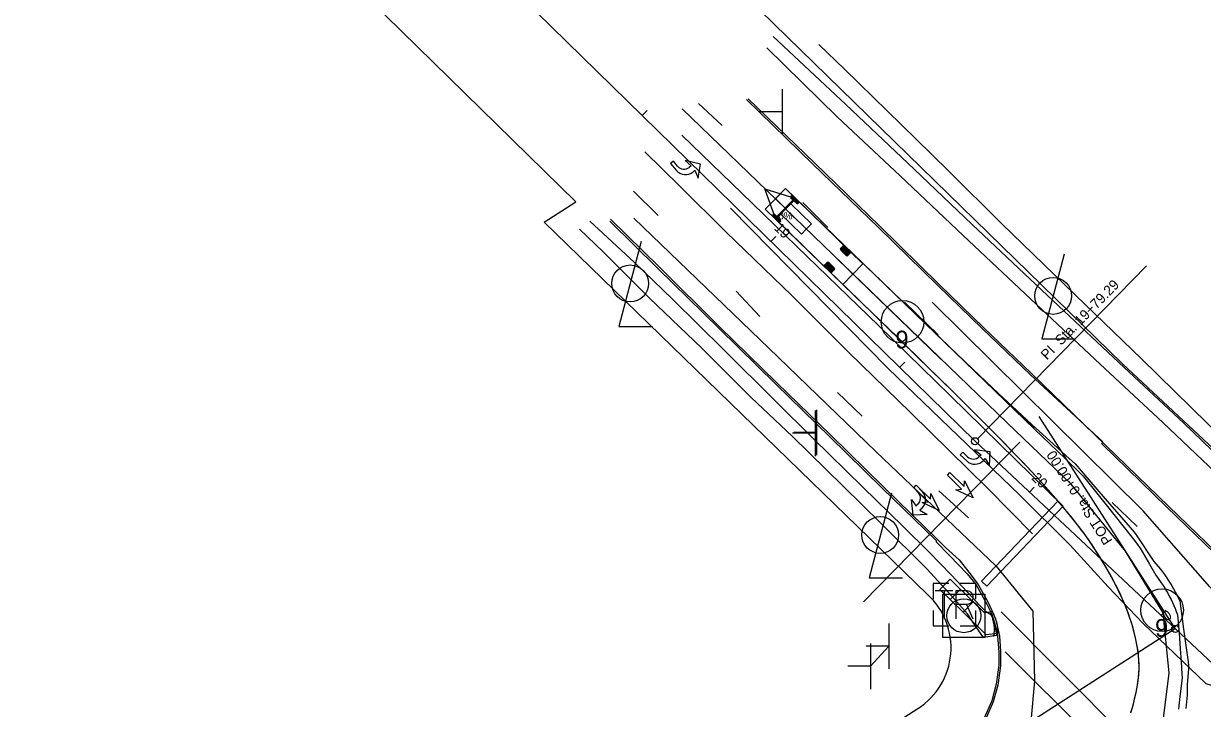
# Model space of a CAD drawing. Extents: x 1475900 to 1484331, y 375914 to 383395.
# Drawn here: x 1479302.4 to 1479629.9, y 379915.4 to 380105.5 of the extents above; entities that cross this region are included whole.
import ezdxf

# ---------------------------------------------------------------- set-up
doc = ezdxf.new("R2010")
doc.units = 0
for name, color, linetype in [('Default', 7, 'Continuous'), ('LT_X_Poles', 7, 'Continuous'), ('PM_X_Cells', 7, 'Continuous'), ('PM_X_Cells (Construction)', 7, 'Continuous'), ('PM_X_Channelizing_Line', 7, 'Continuous'), ('PM_X_CL_Double_Solid', 7, 'Continuous'), ('PM_X_Crosswalk', 7, 'Continuous'), ('PM_X_Lane_Line', 7, 'Continuous'), ('PM_X_Misc', 7, 'Continuous'), ('PM_X_Stop_Line', 7, 'Continuous'), ('PV_X_Curb', 7, 'Continuous'), ('PV_X_Walk', 7, 'Continuous'), ('RW_X_CL_20', 7, 'Continuous'), ('RW_X_Esmt_SH', 7, 'Continuous'), ('RW_X_Esmt_U', 7, 'Continuous'), ('RW_X_Text', 7, 'Continuous'), ('SG_X_Poles', 7, 'Continuous'), ('SG_X_PullBox', 7, 'Continuous'), ('SG_X_PullBox (Construction)', 7, 'Continuous'), ('SN_X_Public', 7, 'Continuous')]:
    doc.layers.add(name, color=color, linetype=linetype)

# ---------------------------------------------------------------- blocks, each defined once
blk = doc.blocks.new('SGN1P')
at = {"layer": 'SN_X_Public'}
for p, q in [((0, 0.02032), (0, -0.02032)), ((0, 0), (-0.02032, 0))]:
    blk.add_line(p, q, dxfattribs=at)
blk = doc.blocks.new('POINT_DISPLAY')
at = {"layer": 'Default'}
blk.add_line((0, 0), (0, 0), dxfattribs=at)
blk = doc.blocks.new('PMTHR')
at = {"layer": 'PM_X_Cells'}
blk.add_lwpolyline([(0, 0), (-1.27, -0.441), (-1.016, -0.127), (-2.413, -0.127), (-2.413, 0.127), (-1.016, 0.127), (-1.27, 0.441)], close=True, dxfattribs=at)
at = {"layer": 'PM_X_Cells (Construction)'}
for p in [(0, 0), (-2.413, 0)]:
    blk.add_blockref('POINT_DISPLAY', p, dxfattribs=at)
blk = doc.blocks.new('PMLFT')
at = {"layer": 'PM_X_Cells'}
for points in [[(-0.569, 0), (-0.569, 0), (-0.569, 0.169), (0, 0), (-0.65, 0.762), (-1.544, 0.085), (-0.975, 0.169), (-0.975, -0.009)], [(-1.559, -0.593), (-2.032, -0.593), (-2.032, -0.847), (-1.402, -0.847)]]:
    blk.add_lwpolyline(points, dxfattribs=at)
for centre, radius, end in [((-1.559, -0.009), 0.583, 0), ((-1.402, -0.013), 0.833, 0.90849)]:
    blk.add_arc(centre, radius, 270, end, dxfattribs=at)
at = {"layer": 'PM_X_Cells (Construction)'}
for p in [(-2.032, 0), (0, 0)]:
    blk.add_blockref('POINT_DISPLAY', p, dxfattribs=at)
blk = doc.blocks.new('LPOLE')
at = {"layer": 'LT_X_Poles'}
blk.add_lwpolyline([(0.01, 0.0375), (-0.01, -0.0385), (0.02, -0.0385)], dxfattribs=at)
blk.add_circle((0, 0), 0.0165, dxfattribs=at)
blk = doc.blocks.new('SPOLE')
at = {"layer": 'SG_X_Poles'}
blk.add_lwpolyline([(-0.0191, -0.0191), (0.019, -0.0191), (0.019, 0.019), (-0.0191, 0.019)], close=True, dxfattribs=at)
blk.add_circle((0, 0), 0.0152, dxfattribs=at)
blk = doc.blocks.new('SIGPB')
at = {"layer": 'SG_X_PullBox'}
for p, q in [((-0.0172, 0.0127), (-0.0014, 0.0127)), ((-0.0092, 0.0127), (-0.0092, -0.0127)), ((0.0108, 0.0003), (0.0164, -0.0127))]:
    blk.add_line(p, q, dxfattribs=at)
for points in [[(-0.0051, 0.019), (-0.019, 0.019), (-0.019, 0.0051)], [(0.0014, -0.0127), (0.0014, 0.0127), (0.011, 0.0127), (0.012, 0.0125), (0.0134, 0.0121), (0.014, 0.0117), (0.0146, 0.0113), (0.0154, 0.0103), (0.016, 0.0093), (0.0164, 0.0077), (0.0164, 0.0053), (0.0162, 0.0045), (0.0158, 0.0033), (0.015, 0.0019), (0.0142, 0.0013), (0.0136, 0.0009), (0.0132, 0.0007), (0.0126, 0.0005), (0.0108, 0.0003), (0.0014, 0.0003)], [(0.019, 0.0051), (0.019, 0.019), (0.0051, 0.019)], [(-0.019, -0.0051), (-0.019, -0.019), (-0.0051, -0.019)], [(0.0051, -0.019), (0.019, -0.019), (0.019, -0.0051)]]:
    blk.add_lwpolyline(points, dxfattribs=at)
at = {"layer": 'SG_X_PullBox (Construction)'}
blk.add_blockref('POINT_DISPLAY', (0, 0), dxfattribs=at)

msp = doc.modelspace()

# ---------------------------------------------------------------- linework, layer by layer
at = {"layer": 'Default'}
for p, q in [((1479535.72, 379945), (1479579.16, 379989.25)), ((1479542.75, 379932.65), (1479537.69, 379927.08))]:
    msp.add_line(p, q, dxfattribs=at)
at = {"layer": 'PM_X_Cells'}
for points in [[(1479564.64, 379985.22), (1479563.29, 379986.5), (1479562.6, 379985.78), (1479564.4, 379984.07)], [(1479569.08, 379984.23), (1479569.08, 379984.23), (1479569.53, 379984.72), (1479570.7, 379982.69), (1479570.91, 379986.63), (1479566.52, 379987.12), (1479568.37, 379985.82), (1479567.89, 379985.31)], [(1479550.93, 379975.28), (1479549.66, 379976.64), (1479550.39, 379977.33), (1479552.08, 379975.52)], [(1479551.89, 379970.85), (1479551.9, 379970.85), (1479551.41, 379970.39), (1479553.43, 379969.21), (1479549.49, 379969.03), (1479549.03, 379973.42), (1479550.31, 379971.56), (1479550.83, 379972.04)]]:
    msp.add_lwpolyline(points, dxfattribs=at)
for centre, radius, start, end in [((1479566.66, 379986.45), 3.28, 226.5201, 317.4286), ((1479566.22, 379986.89), 2.3, 226.5201, 316.5201), ((1479549.26, 379973.71), 2.3, 313.1325, 43.1325), ((1479549.69, 379973.28), 3.28, 312.224, 43.1325)]:
    msp.add_arc(centre, radius, start, end, dxfattribs=at)
at = {"layer": 'PM_X_Channelizing_Line'}
msp.add_lwpolyline([(1479582.67, 379963.81), (1479570.27, 379976.46), (1479548.91, 379997.46), (1479531.64, 380014.2), (1479515.85, 380030.02), (1479497.57, 380047.61), (1479484.7, 380060.36), (1479474.97, 380069.83)], dxfattribs=at)
at = {"layer": 'PM_X_CL_Double_Solid'}
msp.add_lwpolyline([(1479591.18, 379971.53), (1479573.51, 379988.81), (1479559.79, 380002.28), (1479539.85, 380021.68), (1479520.04, 380040.81), (1479501.88, 380058.4), (1479485.22, 380074.47)], dxfattribs=at)
at = {"layer": 'PM_X_Crosswalk'}
for p, q in [((1479636.37, 379879.55), (1479574.01, 379942.24)), ((1479627.79, 379878.68), (1479575.12, 379931.13))]:
    msp.add_line(p, q, dxfattribs=at)
at = {"layer": 'PM_X_Lane_Line'}
for p, q in [((1479489.87, 380083.25), (1479496.48, 380077.17)), ((1479471.84, 380058.98), (1479478.64, 380052.19)), ((1479518.91, 380055.83), (1479525.77, 380048.89)), ((1479500.33, 380031.19), (1479506.91, 380024.21)), ((1479547.14, 380028.17), (1479556.49, 380019.06)), ((1479528.47, 380003.04), (1479535.32, 379996.48)), ((1479576.69, 379999.46), (1479583.1, 379993.39)), ((1479556.63, 379975.74), (1479564.85, 379968.3)), ((1479604.82, 379972.58), (1479611.79, 379965.86))]:
    msp.add_line(p, q, dxfattribs=at)
at = {"layer": 'PM_X_Misc'}
for p, q in [((1479485.35, 380081.84), (1479514.11, 380054.03)), ((1479511.23, 380051.56), (1479516.56, 380056.9)), ((1479516.56, 380051.56), (1479511.23, 380056.9)), ((1479557.24, 380012.32), (1479528.48, 380040.12))]:
    msp.add_line(p, q, dxfattribs=at)
for points in [[(1479519.86, 380048.47), (1479518.47, 380047.03), (1479512.72, 380052.59), (1479511.33, 380051.15), (1479508.35, 380059.58), (1479516.88, 380056.91), (1479515.49, 380055.47), (1479521.25, 380049.91)], [(1479514.01, 380059.68), (1479535.58, 380038.83), (1479532.8, 380035.95), (1479530.01, 380033.08), (1479508.45, 380053.93), (1479511.23, 380056.81)]]:
    msp.add_lwpolyline(points, close=True, dxfattribs=at)
for points in [[(1479609.95, 379914.15), (1479610.41, 379915.64), (1479610.82, 379917.12), (1479611.17, 379918.62), (1479611.34, 379919.37), (1479611.64, 379920.87), (1479611.9, 379922.37), (1479612.01, 379923.12), (1479612.19, 379924.67), (1479612.28, 379926.19), (1479612.3, 379926.95), (1479612.25, 379928.49), (1479612.15, 379930), (1479611.95, 379931.53), (1479611.7, 379933.03), (1479611.4, 379934.52), (1479611.23, 379935.26), (1479610.66, 379937.51), (1479610.23, 379939), (1479609.75, 379940.47), (1479609.51, 379941.2), (1479608.97, 379942.63), (1479608.41, 379944.06), (1479607.81, 379945.46), (1479607.18, 379946.85), (1479606.52, 379948.22), (1479605.83, 379949.58), (1479605.13, 379950.93), (1479604.03, 379952.94), (1479602.88, 379954.93), (1479601.7, 379956.9), (1479600.48, 379958.86), (1479599.22, 379960.79), (1479597.91, 379962.69), (1479596.55, 379964.55), (1479595.16, 379966.39), (1479593.72, 379968.21), (1479591.76, 379970.61), (1479589.75, 379972.98), (1479588.25, 379974.7), (1479586.21, 379976.99), (1479583.63, 379979.81), (1479580.99, 379982.62), (1479578.35, 379985.4), (1479574.6, 379989.26), (1479570.82, 379993.11), (1479565.93, 379998), (1479560.47, 380003.42), (1479554.46, 380009.32), (1479546.21, 380017.37), (1479534.61, 380028.62), (1479514.41, 380048.17), (1479508.45, 380053.93), (1479514.01, 380059.68), (1479543.55, 380031.2), (1479557.19, 380018.1), (1479566.13, 380009.55), (1479573.34, 380002.71), (1479576.98, 379999.3), (1479582.51, 379994.18), (1479587.5, 379989.62), (1479591.94, 379985.61), (1479594.51, 379983.3), (1479595.09, 379982.67), (1479599.48, 379977.51), (1479603.41, 379972.95), (1479608, 379967.67), (1479610.94, 379964.31), (1479611.48, 379963.6), (1479616.41, 379956.2), (1479618.2, 379954.04), (1479618.77, 379953.29), (1479619.33, 379952.54), (1479619.87, 379951.77), (1479620.39, 379950.99), (1479620.9, 379950.2), (1479621.39, 379949.39), (1479621.86, 379948.58), (1479622.32, 379947.76), (1479622.75, 379946.93), (1479623.17, 379946.09), (1479623.57, 379945.24), (1479624.65, 379937.36), (1479625.89, 379928.29), (1479626, 379927.35), (1479626.02, 379926.44), (1479625.63, 379921.93), (1479625.64, 379920.99), (1479625.63, 379920.05), (1479625.6, 379919.11), (1479625.55, 379918.17), (1479625.48, 379917.24), (1479625.38, 379916.3), (1479625.27, 379915.37)], [(1479610.01, 379914.32), (1479610.42, 379915.64), (1479610.79, 379917.01), (1479611.13, 379918.4), (1479611.44, 379919.83), (1479611.71, 379921.28), (1479611.96, 379922.76), (1479612.12, 379923.97), (1479612.23, 379925.19), (1479612.29, 379926.41), (1479612.3, 379927.63), (1479612.25, 379928.85), (1479612.15, 379930.07), (1479611.99, 379931.29), (1479611.77, 379932.67), (1479611.5, 379934.07), (1479611.18, 379935.48), (1479610.82, 379936.9), (1479610.43, 379938.33), (1479610.02, 379939.7), (1479609.57, 379941.04), (1479609.07, 379942.4), (1479608.53, 379943.76), (1479607.95, 379945.13), (1479607.34, 379946.5), (1479606.69, 379947.87), (1479606.01, 379949.24), (1479605.3, 379950.61), (1479604.19, 379952.65), (1479603.02, 379954.69), (1479601.81, 379956.72), (1479600.56, 379958.74), (1479599.74, 379960.01), (1479598.89, 379961.29), (1479598.01, 379962.55), (1479596.64, 379964.44), (1479595.22, 379966.31), (1479593.75, 379968.17), (1479592.25, 379970.02), (1479590.72, 379971.85), (1479589.15, 379973.67), (1479587.02, 379976.08), (1479584.86, 379978.47), (1479582.66, 379980.85), (1479579.87, 379983.8), (1479577.06, 379986.74), (1479573.65, 379990.24), (1479569.63, 379994.3), (1479565.01, 379998.92), (1479559.77, 380004.1), (1479553.34, 380010.41), (1479545.13, 380018.42), (1479533.36, 380029.84), (1479511.33, 380051.15), (1479516.89, 380056.9), (1479583.23, 379992.88), (1479591.71, 379984.73), (1479595.98, 379980.59), (1479596.61, 379979.97), (1479597.17, 379979.32), (1479603.51, 379971.43), (1479607.77, 379966.08), (1479610.97, 379961.99), (1479612.05, 379960.59), (1479612.54, 379959.86), (1479615.18, 379955.4), (1479616.92, 379952.42), (1479618.46, 379950.24), (1479618.95, 379949.49), (1479619.43, 379948.73), (1479619.88, 379947.96), (1479620.33, 379947.18), (1479620.75, 379946.39), (1479621.16, 379945.6), (1479621.55, 379944.79), (1479621.92, 379943.97), (1479622.28, 379943.15), (1479622.62, 379942.32), (1479622.96, 379941.38), (1479623.4, 379936.24), (1479623.74, 379931.9), (1479623.99, 379928.4), (1479624.2, 379924.87), (1479624.25, 379923.94), (1479624.2, 379923.03), (1479623.56, 379918.74), (1479623.5, 379917.85), (1479623.42, 379916.96), (1479623.32, 379916.07), (1479623.2, 379915.18)], [(1479515.46, 380057.44), (1479517.48, 380055.5), (1479517.62, 380055.64), (1479515.6, 380057.59), (1479515.74, 380057.73), (1479517.75, 380055.79), (1479517.8, 380055.83), (1479517.64, 380056.17), (1479516.13, 380057.63), (1479515.79, 380057.78), (1479515.42, 380057.4), (1479515.58, 380057.06), (1479517.09, 380055.6), (1479517.43, 380055.45), (1479517.8, 380055.83)], [(1479510.46, 380052.27), (1479512.47, 380050.32), (1479512.61, 380050.47), (1479510.6, 380052.41), (1479510.73, 380052.56), (1479512.75, 380050.61), (1479512.8, 380050.66), (1479512.64, 380051), (1479511.13, 380052.46), (1479510.78, 380052.6), (1479510.41, 380052.22), (1479510.57, 380051.88), (1479512.08, 380050.42), (1479512.43, 380050.28), (1479512.8, 380050.66)], [(1479529.28, 380042.97), (1479531.3, 380041.02), (1479531.44, 380041.16), (1479529.42, 380043.11), (1479529.56, 380043.25), (1479531.57, 380041.31), (1479531.62, 380041.35), (1479531.46, 380041.69), (1479529.95, 380043.15), (1479529.61, 380043.3), (1479529.24, 380042.92), (1479529.4, 380042.58), (1479530.91, 380041.12), (1479531.25, 380040.97), (1479531.62, 380041.35)], [(1479529.84, 380043.54), (1479531.85, 380041.59), (1479531.99, 380041.74), (1479529.98, 380043.68), (1479530.12, 380043.83), (1479532.13, 380041.88), (1479532.18, 380041.93), (1479532.02, 380042.27), (1479530.51, 380043.73), (1479530.16, 380043.88), (1479529.79, 380043.49), (1479529.95, 380043.15), (1479531.46, 380041.69), (1479531.81, 380041.55), (1479532.18, 380041.93)], [(1479524.83, 380038.37), (1479526.85, 380036.42), (1479526.99, 380036.56), (1479524.97, 380038.51), (1479525.11, 380038.65), (1479527.13, 380036.71), (1479527.17, 380036.75), (1479527.01, 380037.09), (1479525.5, 380038.55), (1479525.16, 380038.7), (1479524.79, 380038.32), (1479524.95, 380037.98), (1479526.46, 380036.52), (1479526.8, 380036.37), (1479527.17, 380036.75)], [(1479525.39, 380038.94), (1479527.4, 380036.99), (1479527.54, 380037.14), (1479525.53, 380039.08), (1479525.67, 380039.23), (1479527.68, 380037.28), (1479527.73, 380037.33), (1479527.57, 380037.67), (1479526.06, 380039.13), (1479525.71, 380039.28), (1479525.34, 380038.89), (1479525.5, 380038.55), (1479527.01, 380037.09), (1479527.36, 380036.95), (1479527.73, 380037.33)]]:
    msp.add_lwpolyline(points, dxfattribs=at)
for centre in [(1479546.56, 380022.7), (1479618.67, 379942.66)]:
    msp.add_circle(centre, 5.91, dxfattribs=at)
at = {"layer": 'PM_X_Stop_Line'}
msp.add_lwpolyline([(1479591.18, 379971.53), (1479589.72, 379972.91), (1479568.52, 379950.67), (1479569.97, 379949.29)], close=True, dxfattribs=at)
at = {"layer": 'PV_X_Curb'}
for points in [[(1479795.99, 380033.19), (1479773.61, 380022.19), (1479753.08, 380012.28), (1479732.58, 380002.19), (1479709.58, 379990.94), (1479686.04, 379979.57), (1479675.42, 379995.64), (1479673.84, 379997.04), (1479672.39, 379997.4), (1479671.07, 379997.48), (1479668.75, 379997.51), (1479666.58, 379997.44), (1479665.26, 379997.43), (1479663.76, 379996.91), (1479662.62, 379996.12), (1479646.81, 379979.59), (1479631.39, 379994.41), (1479612.95, 380012.39), (1479594.61, 380030.05), (1479574.05, 380049.98), (1479559.35, 380064.64), (1479550.33, 380073.36), (1479530.48, 380092.84), (1479523.35, 380099.69)], [(1479638.38, 379953.49), (1479620.03, 379971.27), (1479601.93, 379988.8), (1479602.18, 379989.37), (1479582.14, 380008.01), (1479568.7, 380020.88), (1479556.36, 380032.76), (1479539.92, 380048.83), (1479521.67, 380066.46), (1479503.18, 380084.42)], [(1479638.82, 379953.85), (1479620.56, 379971.48), (1479582.44, 380008.39), (1479569.12, 380021.06), (1479556.79, 380033.03), (1479540.19, 380049.37), (1479522.16, 380066.75), (1479503.68, 380084.63)], [(1479465.22, 380050.65), (1479478.53, 380037.63), (1479495.52, 380020.94), (1479511.46, 380005.33), (1479526.35, 379990.75), (1479540.93, 379976.57), (1479555.93, 379961.97), (1479555.89, 379961.63), (1479559.68, 379957.78), (1479564.54, 379952.78), (1479567.02, 379949.69), (1479570, 379944.36), (1479571.37, 379941.52), (1479571.64, 379940.63), (1479572.4, 379938.2), (1479572.73, 379936.74), (1479572.92, 379935.42), (1479573.29, 379931.12), (1479573.28, 379927.36), (1479572.59, 379922.13), (1479571.4, 379917.5), (1479569.16, 379912.51)], [(1479465.43, 380051.17), (1479478.92, 380037.91), (1479495.63, 380021.43), (1479511.64, 380005.78), (1479526.61, 379991.24), (1479541.43, 379976.72), (1479556.22, 379962.4), (1479558.52, 379960.09), (1479562.26, 379956.63), (1479564.94, 379953.17), (1479567.55, 379949.79), (1479570.39, 379944.78), (1479571.86, 379941.54), (1479572.44, 379940.29), (1479572.89, 379938.33), (1479573.21, 379936.75), (1479573.49, 379935.41), (1479573.82, 379931.24), (1479573.76, 379927.25), (1479573.04, 379921.89), (1479571.77, 379917.23), (1479569.5, 379912.16)], [(1479563.39, 379942.1), (1479566.19, 379944.95), (1479569.22, 379941.97), (1479571.54, 379942.26)], [(1479573.08, 379936.2), (1479569.81, 379935.79), (1479563.39, 379942.1)]]:
    msp.add_lwpolyline(points, dxfattribs=at)
for centre, radius, start, end in [((1479560.49, 379937.18), 11.6, 350.7593, 23.483), ((1479561.98, 379936.61), 11.1, 357.8944, 30.6182)]:
    msp.add_arc(centre, radius, start, end, dxfattribs=at)
at = {"layer": 'PV_X_Walk'}
for p, q in [((1479556.97, 379948.41), (1479559.78, 379951.26)), ((1479566.19, 379944.95), (1479559.78, 379951.26)), ((1479563.39, 379942.1), (1479556.97, 379948.41)), ((1479559.82, 379945.61), (1479562.63, 379948.46))]:
    msp.add_line(p, q, dxfattribs=at)
for points in [[(1479637.77, 379982.02), (1479624.64, 379994.68), (1479608.14, 380010.06), (1479588.42, 380028.53), (1479565.92, 380049.66), (1479549.79, 380065.1), (1479530.81, 380082.98), (1479510.65, 380101.86)], [(1479508.9, 380098.74), (1479528.42, 380079.59), (1479545.91, 380063.23), (1479563.42, 380046.67), (1479583.68, 380027.56), (1479601.43, 380010.98), (1479618.88, 379994.72), (1479633.51, 379980.86), (1479639.16, 379975.37), (1479642.14, 379972.51), (1479646.22, 379969.76), (1479649.18, 379968.04), (1479652.86, 379966.82), (1479656.79, 379966.27), (1479660.63, 379966.35), (1479661.26, 379962.34), (1479661.8, 379958.41), (1479662.4, 379954.37), (1479663.05, 379950.6), (1479663.59, 379946.45), (1479663.66, 379946.47), (1479664.16, 379942.19)], [(1479571.22, 379941.41), (1479571.44, 379940.74), (1479572.05, 379938.94), (1479572.4, 379937.36), (1479572.58, 379936.25), (1479572.71, 379935.62), (1479569.08, 379935.11), (1479567.56, 379937.2), (1479566.03, 379939.55), (1479564.62, 379941.63), (1479559.49, 379947.36), (1479553.28, 379954.09), (1479540.66, 379966.75), (1479530.12, 379977.06), (1479515.96, 379990.9), (1479504.53, 380001.71), (1479490.82, 380015.4), (1479476.31, 380029.29), (1479463.44, 380042.08), (1479456.83, 380048.37)], [(1479459.69, 380050.63), (1479472.08, 380039.16), (1479482.63, 380028.96), (1479496.94, 380014.96), (1479511.11, 380000.89), (1479521.78, 379990.32), (1479535.54, 379976.8), (1479546.78, 379965.86), (1479553.98, 379958.8), (1479560.12, 379952.43), (1479566.08, 379946.06), (1479567.84, 379944.16), (1479569.59, 379942.39), (1479571.25, 379941.41)]]:
    msp.add_lwpolyline(points, dxfattribs=at)
at = {"layer": 'RW_X_CL_20'}
for p, q in [((1479474.27, 380079.94), (1479475.66, 380081.37)), ((1479510.01, 380044.98), (1479511.41, 380046.41)), ((1479567.4, 379990.25), (1479614.35, 380038.25)), ((1479545.76, 380010.02), (1479547.16, 380011.45)), ((1479621.8, 379938.29), (1479584.53, 379996.46)), ((1479581.82, 379975.38), (1479583.18, 379976.84)), ((1479618.32, 379941.21), (1479619.68, 379942.67)), ((1479622.34, 379937.45), (1479341.12, 379757.31)), ((1479622.34, 379937.45), (1479621.26, 379939.13))]:
    msp.add_line(p, q, dxfattribs=at)
msp.add_lwpolyline([(1477185.15, 382318.79), (1478151.68, 381373.49), (1479566.7, 379989.54), (1480555.97, 379063.33), (1481343.87, 378335.5), (1481853.32, 377853.22), (1482587.9, 377143.51), (1482849.67, 376882.07), (1483668.91, 376080.34), (1483878.1, 376026.7), (1484025.82, 375988.83), (1484313.71, 375915.02)], dxfattribs=at)
for centre in [(1479566.7, 379989.54), (1479622.34, 379937.45)]:
    msp.add_circle(centre, 1, dxfattribs=at)
at = {"layer": 'RW_X_Esmt_SH'}
for p, q in [((1479470.26, 380145.01), (1479607.65, 380011.05)), ((1479447.05, 380050.33), (1479553.54, 379946.99)), ((1479607.65, 380011.05), (1479652.81, 379968.89)), ((1479330.33, 379774.15), (1479550.85, 379915.4))]:
    msp.add_line(p, q, dxfattribs=at)
msp.add_lwpolyline([(1477164.17, 382297.34), (1478130.7, 381352.04), (1479455.84, 380056)], dxfattribs=at)
msp.add_arc((1479540.05, 379932.23), 20, 302.6904, 47.5769, dxfattribs=at)
at = {"layer": 'RW_X_Esmt_U'}
msp.add_line((1479447.05, 380050.33), (1479455.84, 380056), dxfattribs=at)
at = {"layer": 'RW_X_Text'}
for points in [[(1479471.95, 380051.45), (1479512.03, 380012.85), (1479539.25, 379986.63), (1479572.54, 379954.89), (1479582.75, 379942.39), (1479583.25, 379923.03), (1479582.2, 379911.73), (1479576.73, 379903.52), (1479558.69, 379891.68), (1479532.63, 379879.98), (1479504.24, 379864.32), (1479478.39, 379850.9), (1479444.42, 379830.31)], [(1479498.76, 380054.27), (1479542.61, 380009.77), (1479579.04, 379974.72), (1479593.11, 379960.7), (1479603.72, 379949.15), (1479613.43, 379938.94), (1479630.83, 379922.33), (1479649.98, 379916.32), (1479663.12, 379916.63), (1479679.72, 379921.61), (1479697.44, 379935.96), (1479749.58, 379962.61), (1479797.99, 379987.23)], [(1479505.69, 379851.09), (1479539.39, 379865.34), (1479567.99, 379878.88), (1479580.84, 379884.45), (1479595.24, 379890.7), (1479602.96, 379893.46), (1479612.47, 379899.63), (1479618.9, 379911.25), (1479620.67, 379925.2), (1479619, 379941.94), (1479608.5, 379959.04), (1479593.41, 379977.66), (1479575.62, 379994.65), (1479545.99, 380023.25), (1479513.89, 380054.23)], [(1479792.31, 379997.56), (1479710.02, 379956.74), (1479682.58, 379943.12), (1479669.95, 379935.54), (1479659.06, 379932.66), (1479645.23, 379935.86), (1479631.96, 379949.18), (1479613.32, 379970.31), (1479554.76, 380028.14)]]:
    msp.add_lwpolyline(points, dxfattribs=at)

# ---------------------------------------------------------------- block references
at = {"layer": 'LT_X_Poles', "xscale": 310.00000000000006, "yscale": 310.00000000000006}
for p in [(1479470.88, 380033.36), (1479588.41, 380029.88), (1479540.37, 379963.53)]:
    msp.add_blockref('LPOLE', p, dxfattribs=at)
at = {"layer": 'PM_X_Cells'}
for name, p, xscale, yscale, rotation in [('PMLFT', (1479489.79, 380062.6), 3.9370078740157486, 3.9370078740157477, -50.63514358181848), ('PMTHR', (1479566.15, 379973.82), 3.937007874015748, 3.937007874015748, -44.669750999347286), ('PMTHR', (1479556.78, 379970.28), 3.9370078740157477, 3.9370078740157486, -44.75356996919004)]:
    msp.add_blockref(name, p, dxfattribs=dict(at, xscale=xscale, yscale=yscale, rotation=rotation))
at = {"layer": 'SG_X_Poles', "xscale": 310.00000000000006, "yscale": 310.00000000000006}
msp.add_blockref('SPOLE', (1479563.59, 379941.13), dxfattribs=at)
at = {"layer": 'SG_X_PullBox', "xscale": 310.00000000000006, "yscale": 310.00000000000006}
msp.add_blockref('SIGPB', (1479561.01, 379944.17), dxfattribs=at)
at = {"layer": 'SN_X_Public', "xscale": 310.00000000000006, "yscale": 310.00000000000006}
for p in [(1479513.17, 380080.99), (1479522.31, 379991.75), (1479522.71, 379991.94), (1479542.75, 379932.65), (1479537.69, 379927.08)]:
    msp.add_blockref('SGN1P', p, dxfattribs=at)

# ---------------------------------------------------------------- texts
at = {"layer": 'PM_X_Misc'}
for s, height, p in [('0%', 2, (1479512.11, 380051.13)), ('9', 4.92, (1479544.59, 380015.31)), ('9', 4.92, (1479616.71, 379935.27))]:
    msp.add_text(s, height=height, dxfattribs=at).set_placement(p)
at = {"layer": 'RW_X_CL_20'}
for s, rotation, p in [('19', 315.636, (1479510.73, 380048.48)), ('PI  Sta. 19+79.29', 45.636, (1479586.68, 380011.96)), ('POT Sta. 0+00.00', 122.6418, (1479604.98, 379961.95)), ('20', 316.8859, (1479582.21, 379979.12)), ('0', 32.6418, (1479619.93, 379939.47))]:
    msp.add_text(s, height=2.8, rotation=rotation, dxfattribs=at).set_placement(p)

doc.saveas('drawing.dxf')
